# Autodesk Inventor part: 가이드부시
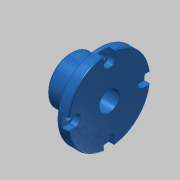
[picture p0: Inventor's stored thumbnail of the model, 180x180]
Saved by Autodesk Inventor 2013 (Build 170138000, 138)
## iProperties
Created: 2019-05
Part Number: 가이드부시
Material: 알루미늄 6061
Document SubType Name: Modeling
Designer: mduedu
Density: 2.71 g/cm^3
Mass: 81.4076 g
Surface Area: 96.2559 cm^2
Volume: 30.0397 cm^3
Author: mduedu
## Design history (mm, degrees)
sketch "스케치1"
  geometry: C1 r 29 at (0, 0); 1 further point
  constraints: 1 centre point, 1 coincident
  dimensions: "d0" = 58 diameter of C1
extrude "돌출1" new body sketch "스케치1" distance "d1" = 7; taper "d2" = 0 deg
sketch "스케치2" dims "d3" = 48
  geometry: L1 (-4, 24)-(-4, 28.723); L2 (4, 24)-(4, 28.723); A1 r 4 centre (0, 24) between (-4, 24) and (4, 24); A2 r 29 centre (0, 0) between (-4, 28.723) and (4, 28.723) reference; A3 r 29 centre (0, 0) between (4, 28.723) and (-4, 28.723); 2 further points
  constraints: 6 point on circle, 4 end point, 2 centre point, 2 coincident, 2 tangent, 2 vertical alignment, 1 parallel, 1 vertical, 2 other
  dimensions: "d4" = 8 distance between parallel lines of L2 L1
extrude "돌출2" cut sketch "스케치2" distance "d5" = 4.4; taper "d6" = 0 deg
fillet "모깎기1" dims "d10" = 1
sketch "스케치3"
  geometry: C1 r 16.5 at (0, 0); 1 further point
  constraints: 1 centre point, 1 coincident
  dimensions: "d11" = 33 diameter of C1
extrude "돌출3" join sketch "스케치3" distance "d12" = 20; taper "d13" = 0 deg
sketch "스케치4"
  geometry: C1 r 7 at (0, 0); 1 further point
  constraints: 1 centre point, 1 coincident
  dimensions: "d14" = 14 diameter of C1
extrude "돌출4" cut sketch "스케치4" stored distance "d15" = 20; taper "d16" = 0 deg
chamfer "모따기1" distance "d17" = 1; stored, may be unused: second distance "d18" = 2, angle "d19" = 45 deg
chamfer "모따기2" distance "d20" = 1; stored, may be unused: second distance "d21" = 2, angle "d22" = 45 deg
sketch "스케치5" dims "d23" = 48
  geometry: 6 further points
  constraints: 2 vertical alignment, 1 coincident, 7 other
  dimensions: "d26" = 360 deg dimension on point (24, 0) point (24, 24) (derived)
sketch "스케치6"
  geometry: 4 further points
  constraints: 4 other
hole "구멍1" sketch "스케치6" at (-24, 24), (-48, 0), (-24, -24), (0, 0) diameter "d28" = 4.5; stored, may be unused: countersink angle "d32" = 90 deg, drill point angle "d34" = 0 deg; dims "d29" = 6, "d30" = 4, "d31" = 2, "d33" = 8
node "솔리드1"
pattern_circular "원형 패턴1" dims angle "d8" = 360 deg
